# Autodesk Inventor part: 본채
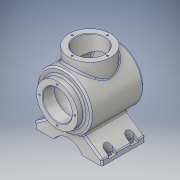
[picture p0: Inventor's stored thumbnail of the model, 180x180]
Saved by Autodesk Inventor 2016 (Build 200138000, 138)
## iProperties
Created: 2021-04
Part Number: 본채
Material: 알루미늄 6061
Document SubType Name: Modeling
Designer: pc-04
Density: 2.7 g/cm^3
Appearance: 알루미늄 - 평지
Mass: 1642.63 g
Surface Area: 1047.47 cm^2
Volume: 608.38 cm^3
Author: pc-04
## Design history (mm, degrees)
sketch "스케치1"
  geometry: L1 (0, 0)-(25.981, 0); L2 (62, 0)-(62, 10); L3 (62, 10)-(26.296, 35); L4 (26.296, 35)-(-26.296, 35); L5 (-26.296, 35)-(-62, 10); L6 (-62, 10)-(-62, 0); L7 (-62, 0)-(-25.981, 0); L8 (-25.981, 0)-(0, 0); L9 (25.981, 0)-(62, 0); A1 r 30 centre (0, -15) between (25.981, 0) and (-25.981, 0); 1 further point
  constraints: 18 end point, 4 collinear, 3 parallel, 2 horizontal, 2 perpendicular, 2 point on circle, 2 vertical alignment, 1 centre point, 1 midpoint, 1 point on line
  dimensions: "d0" = 124 distance between parallel lines of L2 L6; "d1" = 30 radius of A1; "d2" = 15 distance centre to line of A1 L1; "d3" = 10 distance from line of L7 L5.end; "d4" = 10 distance from line of L1 L2.end; "d5" = 55 deg angle of L5 L6; "d6" = 55 deg angle of L3 L2; "d22" = 35 distance between parallel lines of L9 L4
extrude "돌출1" new body sketch "스케치1" stored distance "d8" = 80; taper "d9" = 0 deg
sketch "스케치2"
  geometry: L1 (77, -60)-(77, 60); L2 (77, 60)-(115, 60); L3 (115, 60)-(115, 48); L4 (115, 48)-(127, 48); L5 (127, 48)-(127, -48.336); L6 (104, 60)-(104, 38); L7 (104, 38)-(117, 38); L8 (117, 38)-(117, -41.916); L9 (0, -40)-(0, 40) reference; L10 (0, 40)-(15, 40) reference; A1 r 113 centre (77, 53) between (77, -60) and (127, -48.336); A2 r 103 centre (77, 53) between (77, -50) and (117, -41.916); 1 further point
  constraints: 16 end point, 7 perpendicular, 4 point on circle, 3 point on line, 2 centre point, 1 vertical
  dimensions: "d10" = 100 diameter of L5 L1; "d11" = 76 diameter of L3 L1; "d12" = 120 distance of L1.start L1.end; "d13" = 103 radius of A2; "d14" = 113 radius of A1; "d15" = 12 distance between parallel lines of L4 L2; "d16" = 80 diameter of L8 L1; "d17" = 22 distance between parallel lines of L7 L2; "d18" = 77 distance between parallel lines of L9 L1; "d19" = 20 distance between parallel lines of L2 L10; "d20" = 54 diameter of L6 L1
revolve "회전1" sketch "스케치2" stored, may be unused: angle "d21" = 90 deg
sketch "스케치3"
  geometry: L1 (62, 0)-(25.981, 0) reference; L2 (0, 117)-(38, 117); L3 (38, 117)-(38, 142); L4 (38, 142)-(0, 142); L5 (0, 142)-(0, 117); 4 further points
  constraints: 8 end point, 2 parallel, 2 vertical alignment, 1 horizontal, 1 perpendicular, 1 other
  dimensions: "d29" = 142 distance between parallel lines of L1 L4; "d30" = 76 diameter of L3 L5; "d31" = 25 distance between parallel lines of L2 L4
revolve "회전3" sketch "스케치3" stored, may be unused: angle "d32" = 90 deg
sketch "스케치4"
  geometry: L1 (30, 117)-(38, 117) reference; L2 (38, 117)-(30, 117); L3 (30, 117)-(30, 109.496); L4 (30, 109.496)-(38, 109.496); L5 (38, 109.496)-(38, 117); L6 (0, -28.4)-(0, 170.4) reference; L7 (-38, 117)-(-30, 117); L8 (-30, 117)-(-30, 109.496); L9 (-30, 109.496)-(-38, 109.496); L10 (-38, 109.496)-(-38, 117); L11 (-38, 117)-(-30, 117) reference; A1 r 50 centre (0, 77) between (30, 117) and (38, 109.496) reference; 1 further point
  constraints: 16 end point, 4 parallel, 3 point on circle, 2 horizontal, 2 perpendicular, 1 point on line
  dimensions: "d33" = 8 distance between parallel lines of L5 L3; "d36" = 8 distance between parallel lines of L8 L10
revolve "회전4" stored, may be unused: angle "d34" = 90 deg
revolve "회전5" stored, may be unused: angle "d35" = 90 deg
revolve "회전6" stored, may be unused: angle "d37" = 90 deg
revolve "회전7" stored, may be unused: angle "d38" = 90 deg
hole "구멍1" diameter "d41" = 54; stored, may be unused: countersink angle "d45" = 90 deg, drill point angle "d47" = 0 deg; dims "d39" = 10, "d40" = 10, "d42" = 6, "d43" = 4, "d44" = 2, "d46" = 8
node "작업 평면2"
sketch "스케치5"
  geometry: L1 (-54, -27)-(-62, -27); L2 (-54, -13)-(-62, -13); L3 (-62, 40)-(-62, -40) reference; L4 (-26.694, -40)-(-62, -40) reference; C1 r 4.5 at (-54, -20); A1 r 7 centre (-54, -20) between (-54, -27) and (-54, -13); 1 further point
  constraints: 4 end point, 2 centre point, 2 horizontal, 2 point on circle, 2 point on line, 1 coincident, 1 parallel
  dimensions: "d49" = 14 diameter of A1; "d50" = 8 distance from line of L3 A1.centre; "d51" = 20 distance from line of A1.centre L4; "d52" = 8 distance of L1.start L1.end; "d53" = 9 diameter of C1
extrude "돌출2" cut sketch "스케치5" distance "d54" = 24; taper "d55" = 0 deg
extrude "돌출3" cut sketch "스케치5" stored distance "d56" = 24; taper "d57" = 0 deg
fillet "모깎기1" dims "d61" = 3
fillet "모깎기2" dims "d62" = 3
chamfer "모따기1" distance "d63" = 1; stored, may be unused: second distance "d64" = 2, angle "d65" = 45 deg
chamfer "모따기2" distance "d66" = 1; stored, may be unused: second distance "d67" = 2, angle "d68" = 45 deg
node "작업 평면6"
sketch "스케치8"
  geometry: L1 (50, 0)-(-50, 0); A1 r 50 centre (0, 0) between (50, 0) and (-50, 0) reference; 1 further point
  constraints: 2 end point, 2 horizontal, 2 point on circle
extrude "돌출6" join sketch "스케치8" distance "d79" = 5.5; taper "d80" = 0 deg
sketch "스케치9"
  geometry: C1 r 38 at (0, 0) reference; 2 further points
  constraints: 1 vertical alignment
  dimensions: "d81" = 32.5 distance of point (0, 32.5) C1.centre
hole "구멍2" sketch "스케치9" at (0, 32.5) diameter "d82" = 3.242; stored, may be unused: countersink angle "d86" = 90 deg, drill point angle "d88" = 118 deg; dims "d83" = 8, "d84" = 4, "d85" = 2, "d87" = 10
sketch "스케치10"
  geometry: 2 further points
  constraints: 1 vertical alignment
  dimensions: "d92" = 32.5 distance of point (0, 0) point (0, 32.5)
hole "구멍3" sketch "스케치10" at (0, 32.5) diameter "d93" = 3.242; stored, may be unused: countersink angle "d97" = 90 deg, drill point angle "d99" = 118 deg; dims "d94" = 8, "d95" = 4, "d96" = 2, "d98" = 10
node "솔리드1"
pattern_linear "직사각형 패턴1"
mirror "대칭1"
pattern_circular "원형 패턴1" dims angle "d90" = 360 deg
pattern_circular "원형 패턴2" dims angle "d101" = 360 deg
other parameters: "d78" = -115
